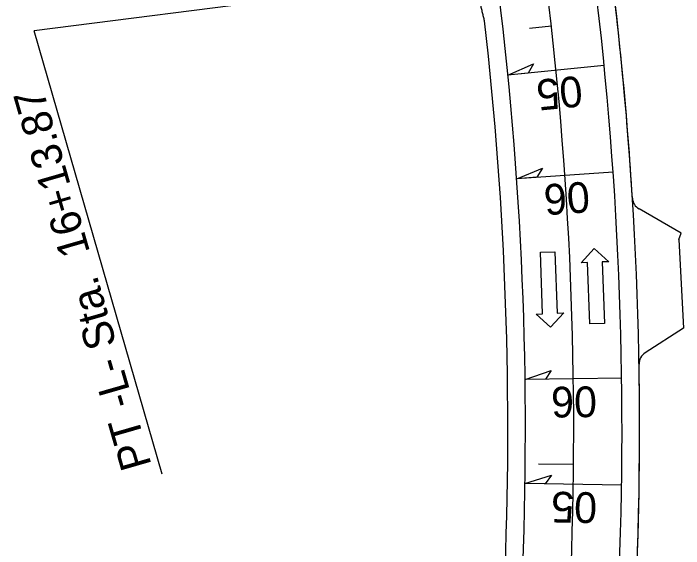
# Model space of a CAD drawing. Extents: x 2167182 to 2168576, y 842635 to 844493.
# Drawn here: x 2167955.9 to 2168108.5, y 843117.4 to 843239.3 of the extents above; entities that cross this region are included whole.
import ezdxf

# ---------------------------------------------------------------- set-up
doc = ezdxf.new("R2010")
doc.units = 0
for name, color, linetype in [('Prop EOT', 7, 'Continuous'), ('Prop Horizontal Alignment', 7, 'Continuous'), ('Prop Horizontal Alignment Station Label', 7, 'Continuous'), ('Prop Horizontal Alignment Tick Large', 7, 'Continuous'), ('Prop Horizontal Alignment Tick Small', 7, 'Continuous'), ('Prop Lane Arrow CELL', 7, 'Continuous'), ('Prop Paved Shoulder', 7, 'Continuous'), ('Prop Shade Light', 7, 'Continuous'), ('Prop Superelevation  Arrow CELL', 7, 'Continuous'), ('Prop Superelevation Label', 7, 'Continuous')]:
    doc.layers.add(name, color=color, linetype=linetype)

msp = doc.modelspace()

# ---------------------------------------------------------------- linework, layer by layer
at = {"layer": 'Prop EOT'}
for radius in [844, 822]:
    msp.add_arc((2167250.45, 843144.63), radius, 357.48556, 7.27898, dxfattribs=at)
at = {"layer": 'Prop Horizontal Alignment'}
msp.add_arc((2167250.45, 843144.63), 833, 357.48556, 7.27898, dxfattribs=at)
at = {"layer": 'Prop Horizontal Alignment Station Label'}
for p in [(2168019.14, 843242.82), (2167989.77, 843134.42)]:
    msp.add_line(p, (2167960.63, 843235.34), dxfattribs=at)
at = {"layer": 'Prop Horizontal Alignment Tick Large'}
msp.add_line((2168083.41, 843136.58), (2168075.41, 843136.66), dxfattribs=at)
at = {"layer": 'Prop Horizontal Alignment Tick Small'}
msp.add_line((2168078.38, 843236.4), (2168073.41, 843235.85), dxfattribs=at)
at = {"layer": 'Prop Lane Arrow CELL'}
for p, q in [((2168075.85, 843184.89), (2168079.14, 843185.02)), ((2168076.37, 843170.9), (2168075.85, 843184.89)), ((2168079.14, 843185.02), (2168079.67, 843171.03)), ((2168085.12, 843182.52), (2168088.1, 843185.78)), ((2168088.1, 843185.78), (2168091.42, 843182.76)), ((2168086.62, 843182.58), (2168085.12, 843182.52)), ((2168087.15, 843168.59), (2168086.62, 843182.58)), ((2168091.42, 843182.76), (2168089.92, 843182.7)), ((2168089.92, 843182.7), (2168090.45, 843168.71)), ((2168081.17, 843171.08), (2168078.19, 843167.82)), ((2168079.67, 843171.03), (2168081.17, 843171.08)), ((2168074.88, 843170.84), (2168076.37, 843170.9)), ((2168078.19, 843167.82), (2168074.88, 843170.84)), ((2168090.45, 843168.71), (2168087.15, 843168.59))]:
    msp.add_line(p, q, dxfattribs=at)
at = {"layer": 'Prop Paved Shoulder'}
for p, q in [((2168107.95, 843189.28), (2168098.32, 843194.77)), ((2168107.42, 843187.83), (2168107.95, 843189.28)), ((2168107.42, 843187.83), (2168108.47, 843167.66)), ((2168108.47, 843167.66), (2168099.69, 843162))]:
    msp.add_line(p, q, dxfattribs=at)
for centre, radius, start, end in [((2167250.45, 843144.63), 848, 3.55368, 7.27898), ((2167250.45, 843144.63), 818, 357.48556, 6.52426), ((2168099.81, 843197.38), 3, 183.5537, 240.2727), ((2168101.32, 843159.48), 3, 122.8119, 181), ((2167250.45, 843144.63), 848, 357.48556, 1)]:
    msp.add_arc(centre, radius, start, end, dxfattribs=at)
msp.add_spline([(2168063.15, 843237.58), (2168063.03, 843238.04), (2168062.92, 843238.51), (2168062.8, 843238.98), (2168062.69, 843239.45), (2168062.57, 843239.91), (2168062.46, 843240.38), (2168062.34, 843240.85), (2168062.22, 843241.31), (2168062.11, 843241.78), (2168061.99, 843242.25), (2168061.87, 843242.71), (2168061.75, 843243.18), (2168061.64, 843243.65), (2168061.52, 843244.11), (2168061.4, 843244.58), (2168061.28, 843245.05), (2168061.16, 843245.51), (2168061.04, 843245.98), (2168060.92, 843246.44), (2168060.8, 843246.91), (2168060.68, 843247.37), (2168060.56, 843247.84), (2168060.44, 843248.31), (2168060.32, 843248.78), (2168060.2, 843249.26), (2168060.07, 843249.73), (2168059.95, 843250.21), (2168059.83, 843250.68), (2168059.71, 843251.16), (2168059.59, 843251.63), (2168059.46, 843252.11), (2168059.34, 843252.58), (2168059.22, 843253.06), (2168059.1, 843253.53), (2168058.98, 843254.01), (2168058.85, 843254.48), (2168058.73, 843254.96), (2168058.61, 843255.43), (2168058.49, 843255.91), (2168058.37, 843256.38), (2168058.24, 843256.86), (2168058.12, 843257.33), (2168058, 843257.81), (2168057.88, 843258.28), (2168057.76, 843258.76), (2168057.63, 843259.23), (2168057.51, 843259.71), (2168057.39, 843260.18), (2168057.27, 843260.66), (2168057.15, 843261.13), (2168057.02, 843261.61), (2168056.9, 843262.08), (2168056.78, 843262.56), (2168056.66, 843263.03), (2168056.54, 843263.51), (2168056.42, 843263.98), (2168056.29, 843264.45), (2168056.17, 843264.93), (2168056.05, 843265.4), (2168055.93, 843265.88), (2168055.81, 843266.35), (2168055.68, 843266.83), (2168055.56, 843267.3), (2168055.44, 843267.78), (2168055.32, 843268.25), (2168055.2, 843268.73), (2168055.07, 843269.2), (2168054.95, 843269.68), (2168054.83, 843270.15), (2168054.71, 843270.63), (2168054.59, 843271.1), (2168054.46, 843271.58), (2168054.22, 843272.53)], degree=3, dxfattribs=at)
at = {"layer": 'Prop Shade Light'}
for radius, end in [(848, 7.27898), (844, 7.27898), (822, 7.27898), (818, 6.52426)]:
    msp.add_arc((2167250.45, 843144.63), radius, 357.48556, end, dxfattribs=at)
msp.add_spline([(2168063.15, 843237.58), (2168063.03, 843238.04), (2168062.92, 843238.51), (2168062.8, 843238.98), (2168062.69, 843239.45), (2168062.57, 843239.91), (2168062.46, 843240.38), (2168062.34, 843240.85), (2168062.22, 843241.31), (2168062.11, 843241.78), (2168061.99, 843242.25), (2168061.87, 843242.71), (2168061.75, 843243.18), (2168061.64, 843243.65), (2168061.52, 843244.11), (2168061.4, 843244.58), (2168061.28, 843245.05), (2168061.16, 843245.51), (2168061.04, 843245.98), (2168060.92, 843246.44), (2168060.8, 843246.91), (2168060.68, 843247.37), (2168060.56, 843247.84), (2168060.44, 843248.31), (2168060.32, 843248.78), (2168060.2, 843249.26), (2168060.07, 843249.73), (2168059.95, 843250.21), (2168059.83, 843250.68), (2168059.71, 843251.16), (2168059.59, 843251.63), (2168059.46, 843252.11), (2168059.34, 843252.58), (2168059.22, 843253.06), (2168059.1, 843253.53), (2168058.98, 843254.01), (2168058.85, 843254.48), (2168058.73, 843254.96), (2168058.61, 843255.43), (2168058.49, 843255.91), (2168058.37, 843256.38), (2168058.24, 843256.86), (2168058.12, 843257.33), (2168058, 843257.81), (2168057.88, 843258.28), (2168057.76, 843258.76), (2168057.63, 843259.23), (2168057.51, 843259.71), (2168057.39, 843260.18), (2168057.27, 843260.66), (2168057.15, 843261.13), (2168057.02, 843261.61), (2168056.9, 843262.08), (2168056.78, 843262.56), (2168056.66, 843263.03), (2168056.54, 843263.51), (2168056.42, 843263.98), (2168056.29, 843264.45), (2168056.17, 843264.93), (2168056.05, 843265.4), (2168055.93, 843265.88), (2168055.81, 843266.35), (2168055.68, 843266.83), (2168055.56, 843267.3), (2168055.44, 843267.78), (2168055.32, 843268.25), (2168055.2, 843268.73), (2168055.07, 843269.2), (2168054.95, 843269.68), (2168054.83, 843270.15), (2168054.71, 843270.63), (2168054.59, 843271.1), (2168054.46, 843271.58), (2168054.22, 843272.53)], degree=3, dxfattribs=at)
at = {"layer": 'Prop Superelevation  Arrow CELL'}
for p, q in [((2168090.38, 843227.4), (2168068.48, 843225.24)), ((2168092.41, 843203.17), (2168070.47, 843201.64)), ((2168094.37, 843156.23), (2168072.37, 843155.92)), ((2168094.35, 843131.91), (2168072.35, 843132.24))]:
    msp.add_line(p, q, dxfattribs=at)
for points in [[(2168068.48, 843225.24), (2168074.26, 843227.82), (2168073.09, 843225.7)], [(2168070.47, 843201.64), (2168076.31, 843204.06), (2168075.08, 843201.97)], [(2168072.37, 843155.92), (2168078.34, 843158.01), (2168076.99, 843155.99)], [(2168072.35, 843132.24), (2168078.38, 843134.15), (2168076.98, 843132.17)]]:
    msp.add_lwpolyline(points, close=True, dxfattribs=at)

# ---------------------------------------------------------------- texts
at = {"layer": 'Prop Horizontal Alignment Station Label'}
msp.add_text('PT -L- Sta.  16+13.87', height=7, rotation=106.1042, dxfattribs=at).set_placement((2167987.36, 843136.47))
at = {"layer": 'Prop Superelevation Label'}
for s, rotation, p in [('05', 185.628, (2168085.06, 843225.12)), ('06', 183.9772, (2168086.84, 843201.03)), ('06', 180.7871, (2168088.68, 843154.4)), ('05', 179.1363, (2168088.81, 843130.24))]:
    msp.add_text(s, height=7, rotation=rotation, dxfattribs=at).set_placement(p)

doc.saveas('drawing.dxf')
